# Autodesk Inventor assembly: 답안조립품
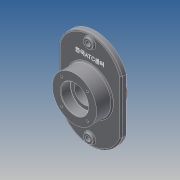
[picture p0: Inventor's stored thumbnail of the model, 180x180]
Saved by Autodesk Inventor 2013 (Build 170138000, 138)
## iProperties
Created: 2015-02
Part Number: 답안조립품
Document SubType Name: Assembly
Designer: kb543-18
Author: kb543-18
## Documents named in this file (2)
- C:\Users\kb543-18\Desktop\450207V1025\답안조립품.iam
- C:\Users\kb543-18\Desktop\450207V1025\1-본체.ipt
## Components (1 placed, 1 different names)
1. 1-본체:1
